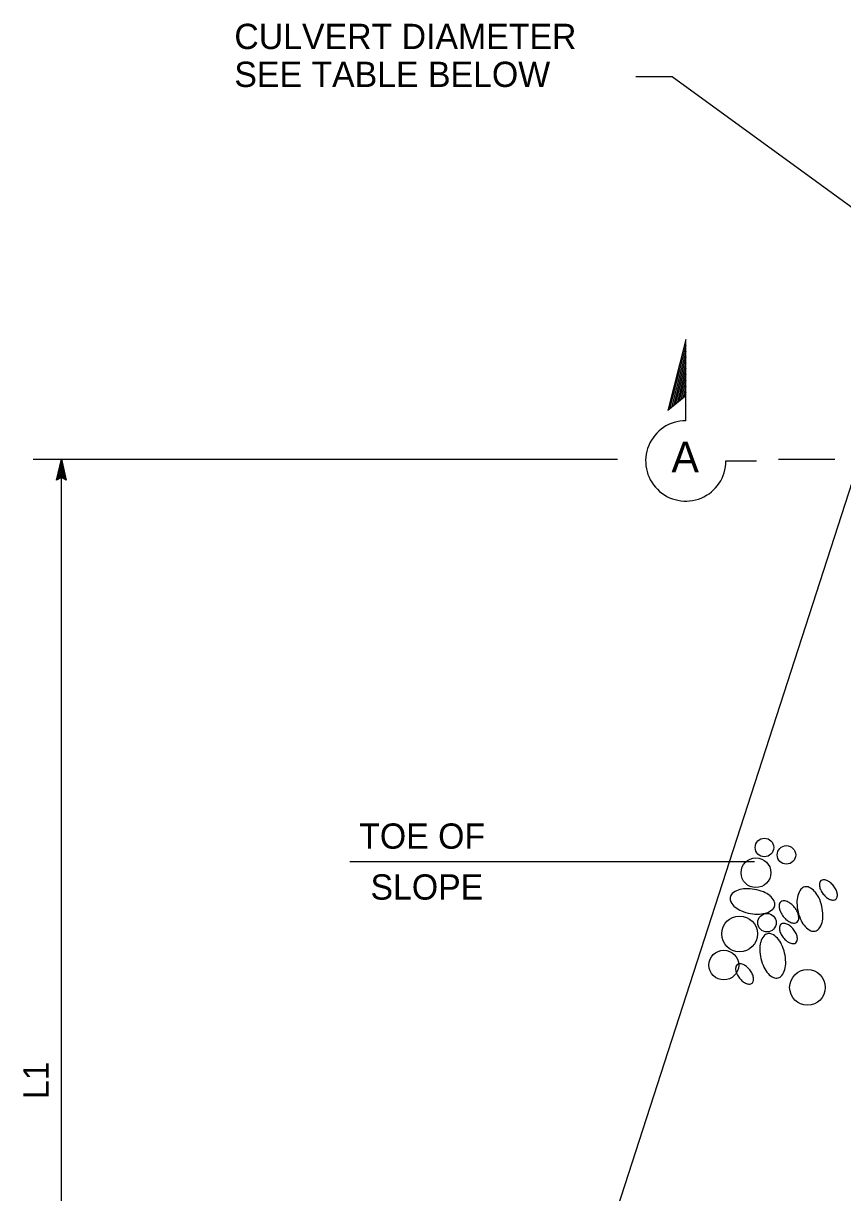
# Model space of a CAD drawing. Extents: x 6707692 to 6708868, y 1870875 to 1871658.
# Drawn here: x 6707717.6 to 6707908.7, y 1871187.6 to 1871460.4 of the extents above; entities that cross this region are included whole.
import ezdxf

# ---------------------------------------------------------------- set-up
doc = ezdxf.new("R2010")
doc.units = 0
doc.layers.add('Level 60', color=7, linetype='Continuous')

msp = doc.modelspace()

# ---------------------------------------------------------------- linework, layer by layer
at = {"layer": 'Level 60'}
for p, q in [((6707872.09, 1871386.66), (6707867.87, 1871370.1)), ((6707872.09, 1871385.3), (6707868.31, 1871370.46)), ((6707872.09, 1871367.69), (6707872.09, 1871386.66)), ((6707872.09, 1871383.94), (6707868.75, 1871370.81)), ((6707872.09, 1871382.58), (6707869.18, 1871371.17)), ((6707872.09, 1871381.22), (6707869.62, 1871371.52)), ((6707872.09, 1871379.86), (6707870.06, 1871371.88)), ((6707872.09, 1871378.49), (6707870.5, 1871372.23)), ((6707872.09, 1871377.13), (6707870.93, 1871372.58)), ((6707872.09, 1871373.52), (6707867.87, 1871370.1)), ((6707872.09, 1871375.77), (6707871.37, 1871372.94)), ((6707872.09, 1871374.41), (6707871.81, 1871373.29)), ((6707719.84, 1871358.74), (6707856.15, 1871358.74)), ((6707725.34, 1871353.83), (6707726.44, 1871358.74)), ((6707725.63, 1871354.01), (6707726.44, 1871357.61)), ((6707726.44, 1871070.4), (6707726.44, 1871358.74)), ((6707726.44, 1871358.74), (6707726.44, 1871356.95)), ((6707726.44, 1871358.74), (6707726.44, 1871358.74)), ((6707726.44, 1871358.74), (6707727.53, 1871353.83)), ((6707726.44, 1871357.6), (6707727.24, 1871354.02)), ((6707912.57, 1871358.74), (6707819.35, 1871070.4)), ((6707881.46, 1871358.33), (6707888.58, 1871358.33)), ((6707893.69, 1871358.74), (6707906.82, 1871358.74)), ((6707726.44, 1871354.48), (6707725.34, 1871353.83)), ((6707725.93, 1871354.2), (6707726.44, 1871356.48)), ((6707726.21, 1871354.34), (6707726.44, 1871355.35)), ((6707726.44, 1871356.48), (6707726.95, 1871354.17)), ((6707726.44, 1871355.35), (6707726.66, 1871354.36)), ((6707727.53, 1871353.83), (6707726.44, 1871354.48)), ((6707725.34, 1871353.83), (6707725.34, 1871353.83)), ((6707727.53, 1871353.83), (6707727.53, 1871353.83)), ((6707793.69, 1871264.9), (6707888.08, 1871264.9))]:
    msp.add_line(p, q, dxfattribs=at)
msp.add_lwpolyline([(6707860.44, 1871448.01), (6707868.88, 1871448.01), (6707937.98, 1871397.77)], dxfattribs=at)
for centre, radius in [((6707890.43, 1871268.13), 2.16), ((6707895.56, 1871266.41), 2.16), ((6707888.45, 1871262.25), 3.47), ((6707884.63, 1871247.97), 4.16), ((6707891.02, 1871250.59), 2.16), ((6707880.95, 1871240.7), 3.47), ((6707900.47, 1871235.49), 4.16)]:
    msp.add_circle(centre, radius, dxfattribs=at)
for centre, radius, start, end in [((6707872.09, 1871358.33), 9.37, 90, 0.0005), ((6707900.19, 1871257.36), 1.61, 103.3223, 140.9226), ((6707900.19, 1871257.36), 1.61, 65.722, 103.3223), ((6707899.28, 1871255.34), 3.82, 41.5964, 65.722), ((6707905.26, 1871259.42), 2.01, 165.2987, 189.5193), ((6707906.48, 1871259.63), 3.25, 189.5193, 205.5514), ((6707904.17, 1871259.71), 0.886, 128.4436, 165.2987), ((6707904.17, 1871259.71), 0.886, 91.5884, 128.4436), ((6707904.2, 1871258.58), 2.01, 67.3678, 91.5884), ((6707903.73, 1871257.44), 3.25, 51.3357, 67.3678), ((6707902.62, 1871256.06), 5.01, 38.4436, 51.3357), ((6707902.62, 1871256.06), 5.01, 25.5514, 38.4436), ((6707884.01, 1871256.18), 1.61, 170.0953, 207.6956), ((6707884.01, 1871256.18), 1.61, 132.495, 170.0953), ((6707885.5, 1871254.55), 3.82, 108.3694, 132.495), ((6707886.28, 1871252.21), 6.29, 92.6551, 108.3694), ((6707886.44, 1871248.68), 9.82, 80.0953, 92.6551), ((6707886.44, 1871248.68), 9.82, 67.5355, 80.0953), ((6707887.79, 1871251.95), 6.29, 51.8212, 67.5355), ((6707889.32, 1871253.88), 3.82, 27.6956, 51.8212), ((6707904.29, 1871255.33), 6.29, 165.0482, 180.7625), ((6707901.91, 1871255.97), 3.82, 140.9226, 165.0482), ((6707897.44, 1871253.71), 6.29, 25.8821, 41.5964), ((6707894.26, 1871252.17), 9.82, 13.3223, 25.8821), ((6707908.07, 1871260.39), 5.01, 205.5514, 218.4436), ((6707908.07, 1871260.39), 5.01, 218.4436, 231.3357), ((6707906.97, 1871259.01), 3.25, 231.3357, 247.3678), ((6707906.52, 1871256.74), 0.886, 271.5884, 308.4436), ((6707906.52, 1871256.74), 0.886, 308.4436, 345.2987), ((6707904.21, 1871256.82), 3.25, 9.5193, 25.5514), ((6707905.43, 1871257.03), 2.01, 345.2987, 9.5193), ((6707885.97, 1871257.21), 3.82, 207.6956, 231.8212), ((6707887.49, 1871259.15), 6.29, 231.8212, 247.5355), ((6707888.84, 1871262.41), 9.82, 247.5355, 260.0953), ((6707889.78, 1871256.55), 3.82, 288.3694, 312.495), ((6707891.28, 1871254.91), 1.61, 312.495, 350.0953), ((6707891.28, 1871254.91), 1.61, 350.0953, 27.6956), ((6707896.04, 1871254.4), 2.21, 165.2987, 189.5193), ((6707897.38, 1871254.63), 3.57, 189.5193, 205.5514), ((6707894.84, 1871254.72), 0.975, 128.4436, 165.2987), ((6707894.84, 1871254.72), 0.975, 91.5884, 128.4436), ((6707894.87, 1871253.48), 2.21, 67.3678, 91.5884), ((6707894.35, 1871252.22), 3.57, 51.3357, 67.3678), ((6707893.14, 1871250.71), 5.51, 38.4436, 51.3357), ((6707893.14, 1871250.71), 5.51, 25.5514, 38.4436), ((6707907.82, 1871255.38), 9.82, 180.7625, 193.3223), ((6707894.26, 1871252.17), 9.82, 0.7625, 13.3223), ((6707906.49, 1871257.87), 2.01, 247.3678, 271.5884), ((6707888.84, 1871262.41), 9.82, 260.0953, 272.6551), ((6707889, 1871258.88), 6.29, 272.6551, 288.3694), ((6707899.13, 1871255.46), 5.51, 205.5514, 218.4436), ((6707899.13, 1871255.46), 5.51, 218.4436, 231.3357), ((6707897.92, 1871253.95), 3.57, 231.3357, 247.3678), ((6707897.39, 1871252.69), 2.21, 247.3678, 271.5884), ((6707897.43, 1871251.45), 0.975, 271.5884, 308.4436), ((6707897.43, 1871251.45), 0.975, 308.4436, 345.2987), ((6707894.89, 1871251.54), 3.57, 9.5193, 25.5514), ((6707907.82, 1871255.38), 9.82, 193.3223, 205.8821), ((6707896.23, 1871251.77), 2.21, 345.2987, 9.5193), ((6707904.64, 1871253.84), 6.29, 205.8821, 221.5964), ((6707900.17, 1871251.58), 3.82, 320.9226, 345.0482), ((6707897.79, 1871252.21), 6.29, 345.0482, 0.7625), ((6707891.52, 1871246.44), 1.61, 103.3223, 140.9226), ((6707891.52, 1871246.44), 1.61, 65.722, 103.3223), ((6707890.61, 1871244.42), 3.82, 41.5964, 65.722), ((6707895.93, 1871249.26), 2.01, 165.2987, 189.5193), ((6707897.15, 1871249.46), 3.25, 189.5193, 205.5514), ((6707894.84, 1871249.55), 0.886, 128.4436, 165.2987), ((6707898.74, 1871250.23), 5.01, 205.5514, 218.4436), ((6707894.84, 1871249.55), 0.886, 91.5884, 128.4436), ((6707894.87, 1871248.42), 2.01, 67.3678, 91.5884), ((6707894.39, 1871247.28), 3.25, 51.3357, 67.3678), ((6707893.29, 1871245.9), 5.01, 38.4436, 51.3357), ((6707893.29, 1871245.9), 5.01, 25.5514, 38.4436), ((6707894.88, 1871246.66), 3.25, 9.5193, 25.5514), ((6707902.8, 1871252.2), 3.82, 221.5964, 245.722), ((6707901.89, 1871250.18), 1.61, 245.722, 283.3223), ((6707901.89, 1871250.18), 1.61, 283.3223, 320.9226), ((6707895.62, 1871244.41), 6.29, 165.0482, 180.7625), ((6707893.24, 1871245.05), 3.82, 140.9226, 165.0482), ((6707888.76, 1871242.79), 6.29, 25.8821, 41.5964), ((6707885.58, 1871241.25), 9.82, 13.3223, 25.8821), ((6707898.74, 1871250.23), 5.01, 218.4436, 231.3357), ((6707897.63, 1871248.85), 3.25, 231.3357, 247.3678), ((6707897.16, 1871247.71), 2.01, 247.3678, 271.5884), ((6707897.19, 1871246.58), 0.886, 271.5884, 308.4436), ((6707897.19, 1871246.58), 0.886, 308.4436, 345.2987), ((6707896.1, 1871246.87), 2.01, 345.2987, 9.5193), ((6707899.15, 1871244.46), 9.82, 180.7625, 193.3223), ((6707885.58, 1871241.25), 9.82, 0.7625, 13.3223), ((6707885.72, 1871239.82), 2.01, 165.2987, 189.5193), ((6707884.63, 1871240.11), 0.886, 128.4436, 165.2987), ((6707884.63, 1871240.11), 0.886, 91.5884, 128.4436), ((6707884.66, 1871238.98), 2.01, 67.3678, 91.5884), ((6707884.19, 1871237.84), 3.25, 51.3357, 67.3678), ((6707883.08, 1871236.46), 5.01, 38.4436, 51.3357), ((6707899.15, 1871244.46), 9.82, 193.3223, 205.8821), ((6707895.97, 1871242.92), 6.29, 205.8821, 221.5964), ((6707889.12, 1871241.29), 6.29, 345.0482, 0.7625), ((6707886.94, 1871240.02), 3.25, 189.5193, 205.5514), ((6707888.53, 1871240.79), 5.01, 205.5514, 218.4436), ((6707888.53, 1871240.79), 5.01, 218.4436, 231.3357), ((6707883.08, 1871236.46), 5.01, 25.5514, 38.4436), ((6707884.67, 1871237.22), 3.25, 9.5193, 25.5514), ((6707885.89, 1871237.43), 2.01, 345.2987, 9.5193), ((6707894.13, 1871241.28), 3.82, 221.5964, 245.722), ((6707893.22, 1871239.26), 1.61, 245.722, 283.3223), ((6707893.22, 1871239.26), 1.61, 283.3223, 320.9226), ((6707891.5, 1871240.66), 3.82, 320.9226, 345.0482), ((6707887.43, 1871239.41), 3.25, 231.3357, 247.3678), ((6707886.95, 1871238.27), 2.01, 247.3678, 271.5884), ((6707886.98, 1871237.14), 0.886, 271.5884, 308.4436), ((6707886.98, 1871237.14), 0.886, 308.4436, 345.2987)]:
    msp.add_arc(centre, radius, start, end, dxfattribs=at)

# ---------------------------------------------------------------- texts
for s, height, p in [('CULVERT DIAMETER', 5.9, (6707766.79, 1871454.43)), ('SEE TABLE BELOW', 5.9, (6707766.79, 1871445.58)), ('A', 7.21, (6707868.73, 1871355.64)), ('TOE OF', 5.9, (6707795.91, 1871267.85)), ('SLOPE', 5.9, (6707798.54, 1871255.97))]:
    msp.add_text(s, height=height, dxfattribs=at).set_placement(p)
msp.add_text('L1', height=5.9, rotation=90, dxfattribs=at).set_placement((6707723.49, 1871209.42))

doc.saveas('drawing.dxf')
